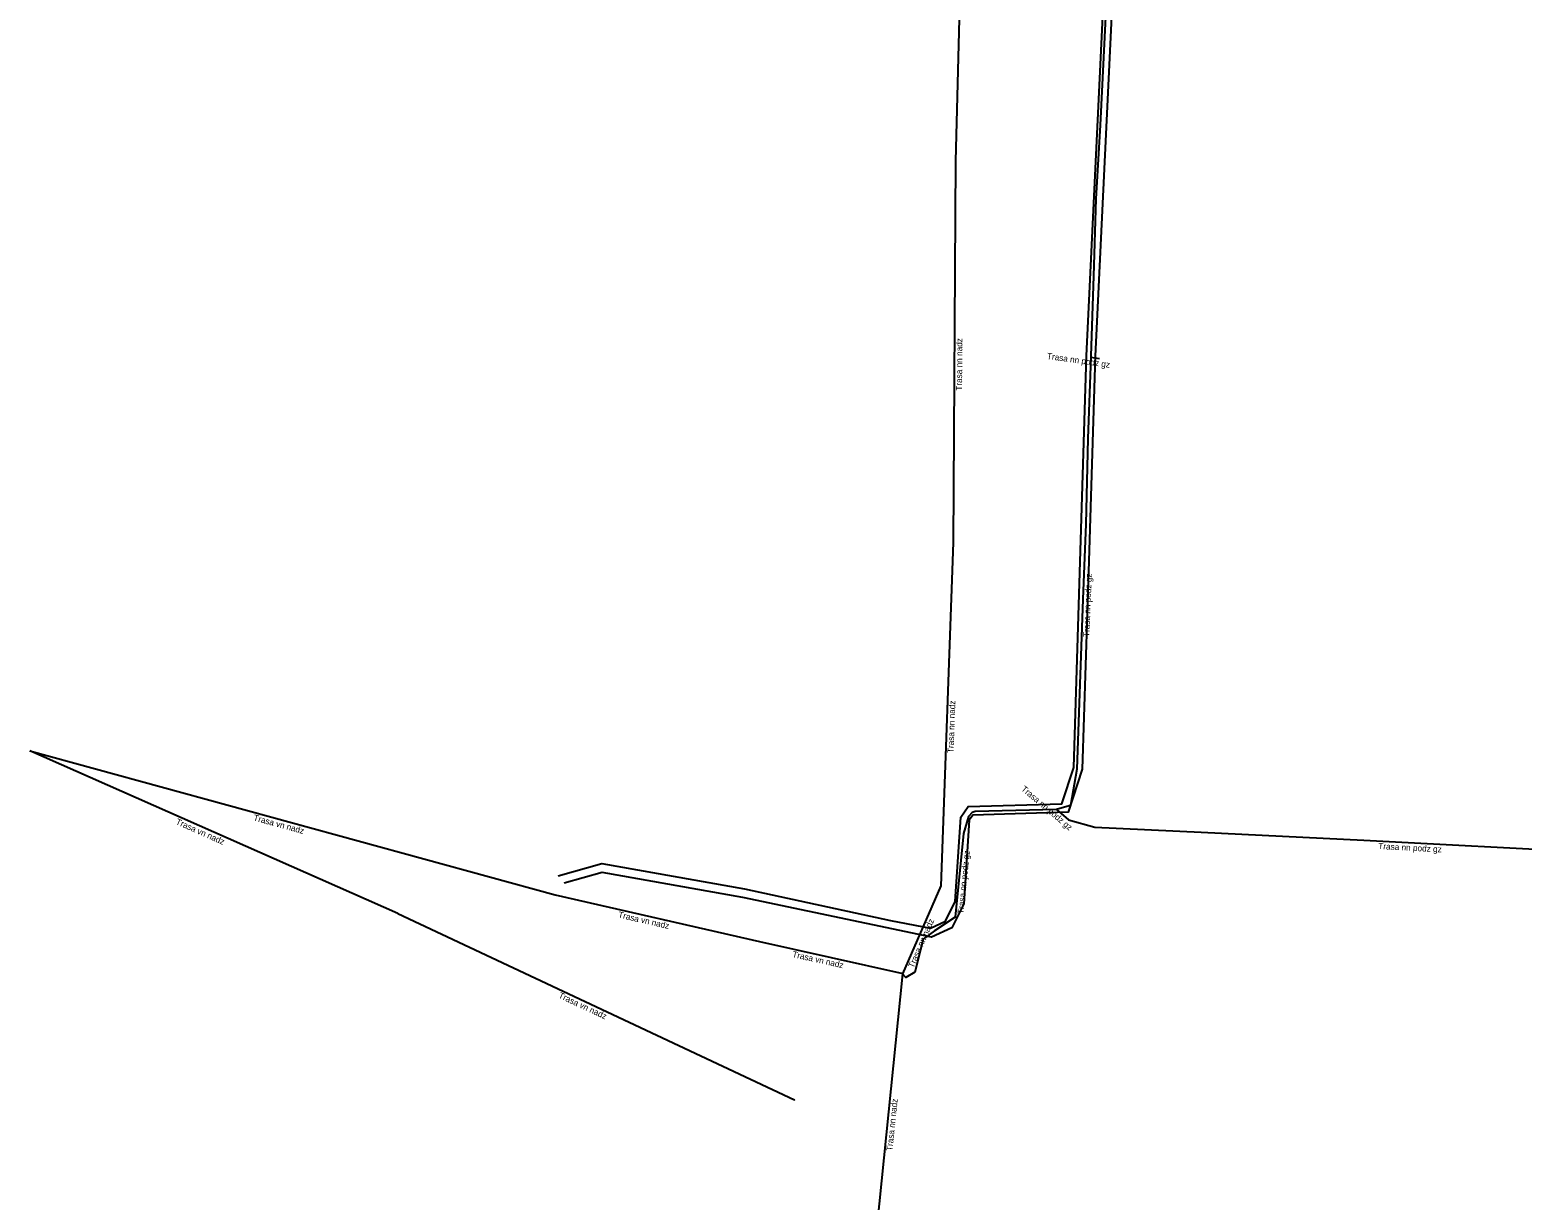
# Model space of a CAD drawing. Extents: x -746878 to -746498, y -1019831 to -1019251.
# Drawn here: x -746798.6 to -746677.2, y -1019547.5 to -1019452.3 of the extents above; entities that cross this region are included whole.
import ezdxf

# ---------------------------------------------------------------- set-up
doc = ezdxf.new("R2010")
doc.units = 0
for name, color, linetype in [('Popiskový text - Ostatní atributy Trasy', 7, 'Continuous'), ('Spojnice NN', 7, 'Continuous'), ('Spojnice VN', 7, 'Continuous')]:
    doc.layers.add(name, color=color, linetype=linetype)

msp = doc.modelspace()

# ---------------------------------------------------------------- linework, layer by layer
at = {"layer": 'Spojnice NN'}
for points in [[(-746708.63, -1019390.81), (-746708.92, -1019398.94), (-746709.15, -1019407.74), (-746709.52, -1019413.78), (-746710.08, -1019428.28), (-746710.38, -1019434.25), (-746710.93, -1019447.39), (-746711.54, -1019460.07), (-746711.88, -1019466.06), (-746712.08, -1019472.33), (-746712.29, -1019478.82), (-746712.29, -1019478.92)], [(-746722.5, -1019431.4), (-746723.3, -1019463)], [(-746723.3, -1019463), (-746723.5, -1019494)], [(-746712.29, -1019478.92), (-746712.53, -1019485.54), (-746712.71, -1019492.5), (-746712.95, -1019498.59), (-746713.43, -1019512.42), (-746713.95, -1019515.38), (-746714.43, -1019515.51), (-746715.1, -1019515.7)], [(-746712.29, -1019478.92), (-746711.6, -1019479.02)], [(-746723.5, -1019494), (-746724.5, -1019521.9)], [(-746715.1, -1019515.7), (-746721.69, -1019515.87), (-746721.94, -1019515.94), (-746722.25, -1019516.28), (-746722.65, -1019517.65), (-746723.33, -1019524.46), (-746725, -1019525.55), (-746725.94, -1019526.25), (-746726.62, -1019528.93), (-746727.34, -1019529.35), (-746727.6, -1019529.06)], [(-746715.1, -1019515.7), (-746714.12, -1019516.53)], [(-746714.12, -1019516.53), (-746711.97, -1019517.13), (-746703.32, -1019517.55), (-746690.1, -1019518.19), (-746671.53, -1019519.18), (-746655.85, -1019520.16)], [(-746724.5, -1019521.9), (-746727.6, -1019529.06)], [(-746727.6, -1019529.06), (-746729.9, -1019551.5)]]:
    msp.add_lwpolyline(points, dxfattribs=at)
at = {"layer": 'Spojnice VN'}
for points in [[(-746755.6, -1019521.1), (-746752.06, -1019520.1), (-746740.46, -1019522.16), (-746728.59, -1019524.73), (-746725.34, -1019525.34), (-746724.12, -1019524.79), (-746723.32, -1019523.18), (-746722.87, -1019516.33), (-746722.26, -1019515.46), (-746714.66, -1019515.24), (-746713.68, -1019512.29), (-746712.64, -1019478.81), (-746711.22, -1019448.9), (-746710.43, -1019427.98), (-746710.03, -1019413.67), (-746709.61, -1019407.69), (-746708.46, -1019380.15), (-746707.88, -1019364.86), (-746707.28, -1019358.02), (-746707.09, -1019352.25), (-746707.09, -1019338.31)], [(-746706.39, -1019338.35), (-746706.39, -1019352.26), (-746706.58, -1019358.06), (-746707.18, -1019364.91), (-746707.76, -1019380.18), (-746708.91, -1019407.73), (-746709.33, -1019413.71), (-746709.73, -1019428.01), (-746710.52, -1019448.93), (-746711.94, -1019478.83), (-746712.47, -1019495.5), (-746712.99, -1019512.41), (-746714.15, -1019515.92), (-746721.89, -1019516.15), (-746722.18, -1019516.57), (-746722.63, -1019523.36), (-746723.6, -1019525.33), (-746725.25, -1019526.07), (-746740.59, -1019522.85), (-746752.02, -1019520.82), (-746755.11, -1019521.69)], [(-746798.56, -1019510.94), (-746755.86, -1019522.63)], [(-746768.63, -1019524.16), (-746798.56, -1019510.94)], [(-746755.86, -1019522.63), (-746739.23, -1019526.44)], [(-746768.63, -1019524.16), (-746736.39, -1019539.29), (-746736.39, -1019539.29)], [(-746739.23, -1019526.44), (-746727.58, -1019529.04), (-746727.6, -1019529.06)]]:
    msp.add_lwpolyline(points, dxfattribs=at)

# ---------------------------------------------------------------- texts
at = {"layer": 'Popiskový text - Ostatní atributy Trasy'}
for s, rotation, p in [('Trasa nn nadz', 89.6304, (-746722.77, -1019481.65)), ('Trasa nn podz gz', 351.8815, (-746715.89, -1019479.06)), ('Trasa nn podz gz', 87.7147, (-746712.42, -1019501.68)), ('Trasa nn nadz', 87.9473, (-746723.46, -1019511.12)), ('Trasa nn podz gz', 319.8056, (-746718, -1019514.1)), ('Trasa vn nadz', 336.1579, (-746786.74, -1019516.87)), ('Trasa vn nadz', 344.6829, (-746780.42, -1019516.58)), ('Trasa nn podz gz', 84.2769, (-746722.65, -1019524.21)), ('Trasa nn podz gz', 356.9673, (-746688.94, -1019518.91)), ('Trasa vn nadz', 347.099, (-746750.76, -1019524.47)), ('Trasa nn nadz', 66.5532, (-746726.71, -1019528.63)), ('Trasa vn nadz', 347.4035, (-746736.6, -1019527.69)), ('Trasa vn nadz', 334.8701, (-746755.63, -1019530.98)), ('Trasa nn nadz', 84.1612, (-746728.43, -1019543.48))]:
    msp.add_text(s, height=0.5, rotation=rotation, dxfattribs=at).set_placement(p)

doc.saveas('drawing.dxf')
